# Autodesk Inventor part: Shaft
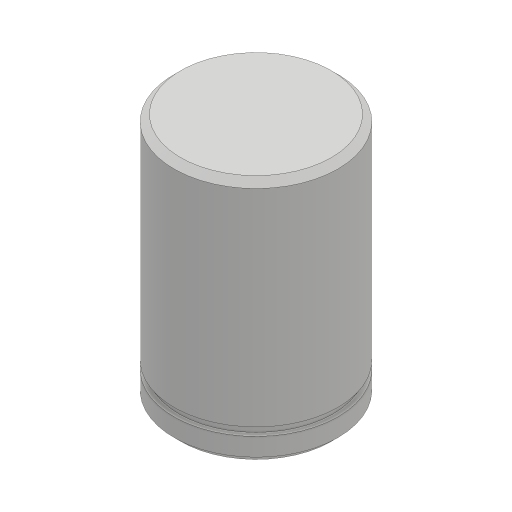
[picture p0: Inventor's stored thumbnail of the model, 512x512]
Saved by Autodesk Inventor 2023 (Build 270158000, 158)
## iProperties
Created: 2016-08
Part Number: Shaft
Material: Generic
Document SubType Name: Modeling
Designer: Sandeep
Density: 1 g/cm^3
Appearance: Default
Author: Sandeep
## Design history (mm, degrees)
sketch "Sketch1"
  geometry: C1 r 25 at (0, 0); 1 further point
  constraints: 1 centre point, 1 coincident
  dimensions: "d0" = 50 diameter of C1
extrude "Extrusion1" new body sketch "Sketch1" stored distance "d1" = 75; taper "d2" = 0 deg
sketch "Sketch2"
  geometry: L1 (-25, -37.5)-(-25, 37.5) reference; L2 (-25, -30)-(-23.5, -30); L3 (-23.5, -30)-(-23.5, -27.5); L4 (-23.5, -27.5)-(-25, -27.5); L5 (-25, -27.5)-(-25, -30); L6 (0, 0)-(0, -83)
  constraints: 10 end point, 2 parallel, 1 horizontal, 1 perpendicular, 1 point on line, 1 vertical
  dimensions: "d3" = 2.5 distance between parallel lines of L2 L4; "d4" = 47 diameter of L3 L6; "d5" = 7.5 distance from line of L2 L1.start
revolve "Revolution1" sketch "Sketch2" stored, may be unused: angle "d6" = 90 deg
chamfer "Chamfer1" distance "d7" = 2; stored, may be unused: second distance "d8" = 2, angle "d9" = 45 deg
body "Solid1"
other parameters: "d10" = 0
